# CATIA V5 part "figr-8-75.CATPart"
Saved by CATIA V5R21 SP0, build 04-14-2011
Part number: Part1
Bounding box of the stored display mesh (mm): x -48 to 48, y -106.879 to 0, z -32.702 to 29.91
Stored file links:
  D:\CATIA V5R21 E-RESOURCES\CATIA-V5R21\catia-v5r21-prt\c08-catia-v5r20-prt\c08-catia-v5r21-figr-8-75.CATPart
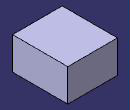
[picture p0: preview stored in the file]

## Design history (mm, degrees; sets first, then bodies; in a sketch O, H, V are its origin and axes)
Body1 (main body)
  Sketch1 on yz-plane, origin (0, 0, 0), H (0, 1, 0), V (0, 0, 1)
    line L1 (-106.8789, 29.9101) -> (0, 29.9101)
    line L2 (0, 29.9101) -> (0, -32.7018)
    line L3 (0, -32.7018) -> (-106.8789, -32.7018)
    line L4 (-106.8789, -32.7018) -> (-106.8789, 29.9101)
    point P3 (0, -32.7018)
    horizontal: L1 H, L3 H
    vertical: L2 V, L4 V
    coincidence: P3 V
  Pad1: profile Sketch1, direction (1, 0, 0), length 48, mirrored extent
Body2
  Sketch2 on yz-plane, origin (0, 0, 0), H (0, 1, 0), V (0, 0, 1)
    line L1 (30, 10) -> (90, 10)
    line L2 (90, 10) -> (90, -10)
    line L3 (90, -10) -> (30, -10)
    line L4 (30, -10) -> (30, 10)
    horizontal: L1 H, L3 H
    vertical: L2 V, L4 V
  Pad2: profile Sketch2, direction (1, 0, 0), length 26, mirrored extent
  Trim1: faces to remove face of Pad2 from Sketch2.L1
